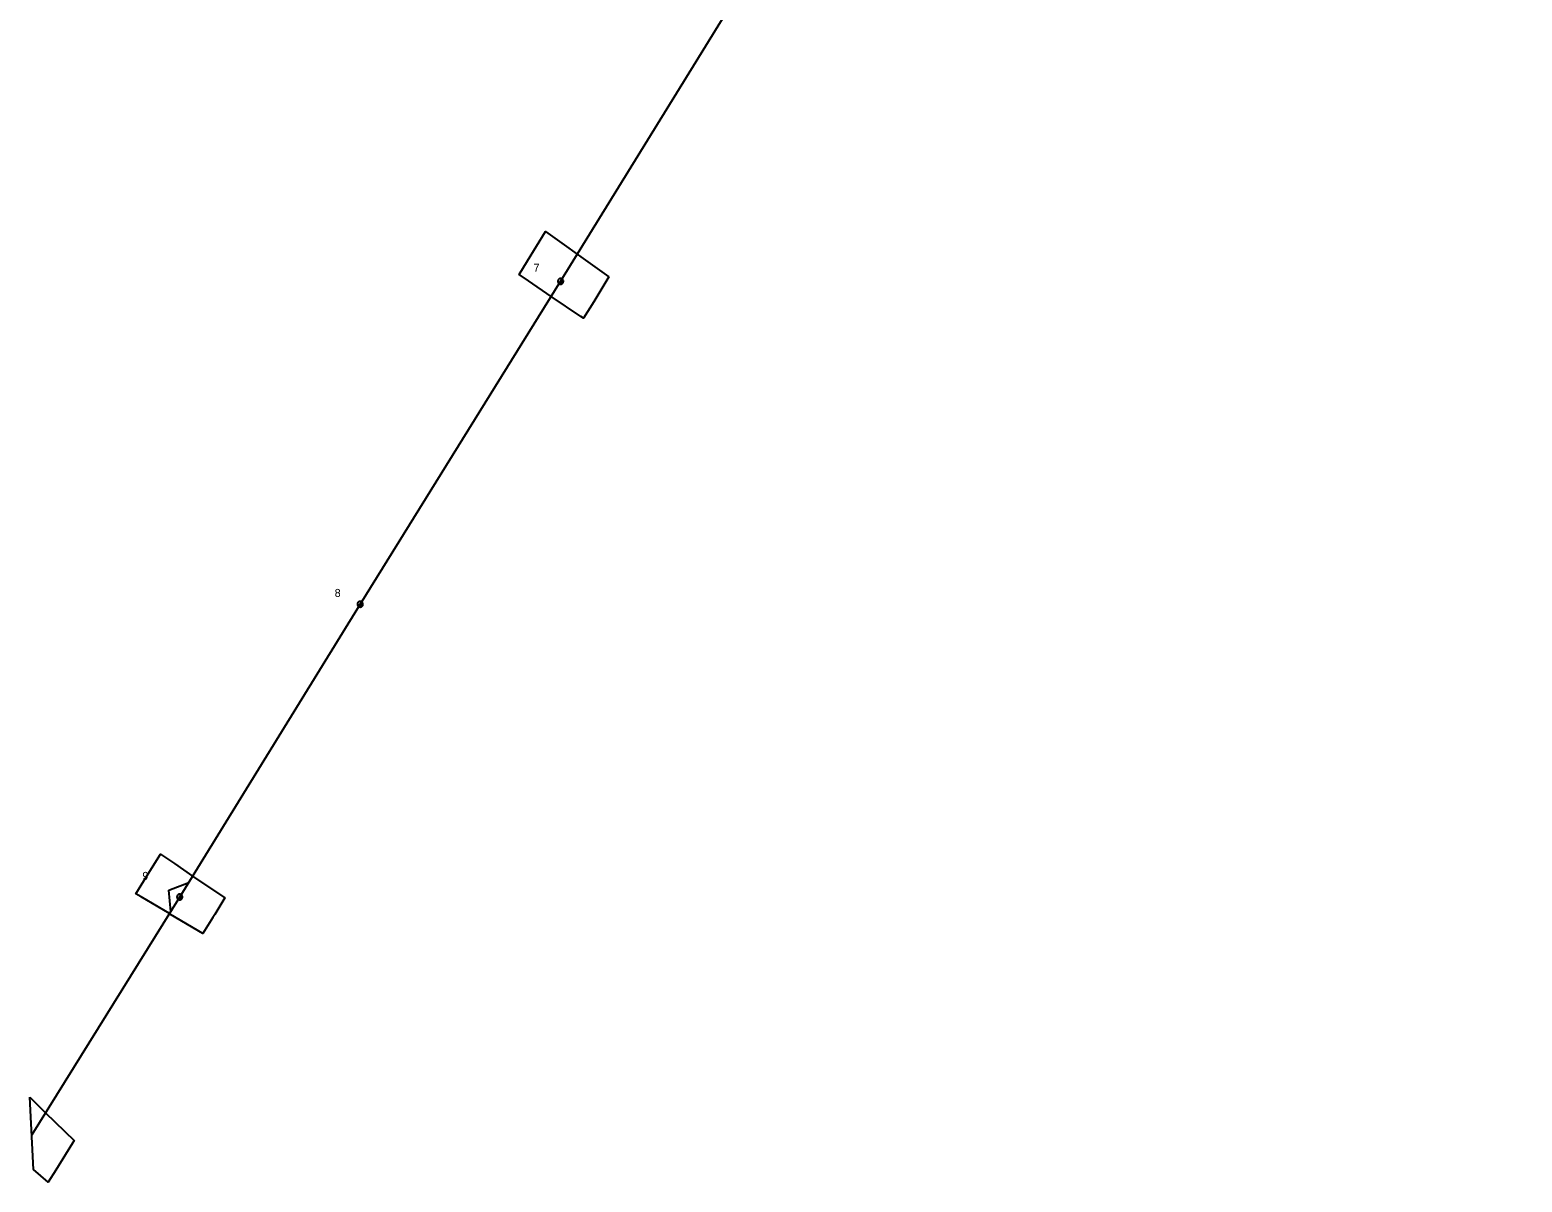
# Model space of a CAD drawing. Extents: x -545588 to -543214, y -1196037 to -1194452.
# Drawn here: x -545558 to -545231.7, y -1195446 to -1195194.1 of the extents above; entities that cross this region are included whole.
import ezdxf

# ---------------------------------------------------------------- set-up
doc = ezdxf.new("R2010")
doc.units = 0
for name, color, linetype in [('Vrstva 1', 7, 'Continuous'), ('Vrstva 13', 7, 'Continuous'), ('Vrstva 14', 7, 'Continuous'), ('Vrstva 15', 7, 'Continuous'), ('Vrstva 18', 7, 'Continuous'), ('Vrstva 2', 7, 'Continuous'), ('Vrstva 35', 7, 'Continuous')]:
    doc.layers.add(name, color=color, linetype=linetype)

# ---------------------------------------------------------------- blocks, each defined once
blk = doc.blocks.new('VN860')
at = {"layer": 'Vrstva 15'}
for points in [[(-3.74, 0), (0.01, 2.82)], [(0.01, 2.82), (3.76, 0)]]:
    blk.add_lwpolyline(points, dxfattribs=at)
blk = doc.blocks.new('VN440')
at = {"layer": 'Vrstva 2'}
for points in [[(1.22, 0), (1.21, 0.13), (1.19, 0.25), (1.16, 0.38), (1.11, 0.5), (1.05, 0.61), (0.98, 0.72), (0.9, 0.82), (0.81, 0.91), (0.71, 0.99), (0.6, 1.06), (0.49, 1.12), (0.37, 1.16), (0.25, 1.2), (0.12, 1.22), (-0.01, 1.22), (-0.14, 1.22), (-0.26, 1.2), (-0.39, 1.16), (-0.51, 1.12), (-0.62, 1.06), (-0.73, 0.99), (-0.83, 0.91), (-0.92, 0.82), (-1, 0.72), (-1.07, 0.61), (-1.13, 0.5), (-1.18, 0.38), (-1.21, 0.25), (-1.23, 0.13), (-1.24, 0), (-1.23, -0.13), (-1.21, -0.26), (-1.18, -0.38), (-1.13, -0.5), (-1.07, -0.62), (-1, -0.73), (-0.92, -0.83), (-0.83, -0.92), (-0.73, -1), (-0.62, -1.07), (-0.51, -1.13), (-0.39, -1.17), (-0.26, -1.2), (-0.14, -1.23), (-0.01, -1.23), (0.12, -1.23), (0.25, -1.2), (0.37, -1.17), (0.49, -1.13), (0.6, -1.07), (0.71, -1), (0.81, -0.92), (0.9, -0.83), (0.98, -0.73), (1.05, -0.62), (1.11, -0.5), (1.16, -0.38), (1.19, -0.26), (1.21, -0.13), (1.22, 0)], [(-1.24, 0), (1.22, 0)], [(-1.18, -0.34), (1.1, -0.34)], [(-1.01, -0.63), (0.97, -0.63)], [(-0.74, -0.92), (0.68, -0.92)]]:
    blk.add_lwpolyline(points, dxfattribs=at)

msp = doc.modelspace()

# ---------------------------------------------------------------- linework, layer by layer
at = {"layer": 'Vrstva 1'}
msp.add_lwpolyline([(-545231.73, -1194976.58), (-545288.13, -1195044.67), (-545343.3, -1195111.41), (-545397.6, -1195177.04), (-545441.95, -1195249.1), (-545485.78, -1195319.69), (-545525.23, -1195383.69), (-545557.58, -1195435.71)], dxfattribs=at)
at = {"layer": 'Vrstva 35'}
for points in [[(-545431.38, -1195248.15), (-545434.72, -1195253.57), (-545436.95, -1195257.17), (-545437.5, -1195256.8), (-545444, -1195252.4), (-545449.01, -1195249.01), (-545451.04, -1195247.63), (-545449.18, -1195244.63), (-545445.24, -1195238.22), (-545441.15, -1195241.15), (-545438.31, -1195243.18), (-545437.5, -1195243.76)], [(-545517.59, -1195387.5), (-545518, -1195388.17), (-545520.2, -1195391.71), (-545527.23, -1195387.5), (-545527.5, -1195387.34), (-545533.66, -1195383.66), (-545534.8, -1195382.98), (-545532.46, -1195379.22), (-545529.44, -1195374.31), (-545526.39, -1195376.39), (-545522.41, -1195379.11), (-545515.38, -1195383.9)], [(-545558, -1195427.48), (-545555.21, -1195430.21), (-545554.56, -1195430.85), (-545548.34, -1195436.94), (-545548.69, -1195437.5), (-545552.34, -1195443.38), (-545554, -1195446.03), (-545557.2, -1195443.26)]]:
    msp.add_lwpolyline(points, close=True, dxfattribs=at)

# ---------------------------------------------------------------- block references
at = {"layer": 'Vrstva 13', "xscale": 0.5}
for p, yscale, rotation in [((-545441.95, -1195249.1), 0.5, 58.16335559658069), ((-545485.78, -1195319.69), 0.5, 58.34994169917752), ((-545525.23, -1195383.69), 0.49999999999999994, 58.12154437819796)]:
    msp.add_blockref('VN440', p, dxfattribs=dict(at, yscale=yscale, rotation=rotation))
at = {"layer": 'Vrstva 18', "rotation": 58.12190834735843}
msp.add_blockref('VN860', (-545525.23, -1195383.69), dxfattribs=at)

# ---------------------------------------------------------------- texts
at = {"layer": 'Vrstva 14'}
for s, p in [('7', (-545447.88, -1195247.03)), ('8', (-545491.35, -1195318.1)), ('9', (-545533.4, -1195379.96))]:
    msp.add_text(s, height=1.75, dxfattribs=at).set_placement(p)

doc.saveas('drawing.dxf')
